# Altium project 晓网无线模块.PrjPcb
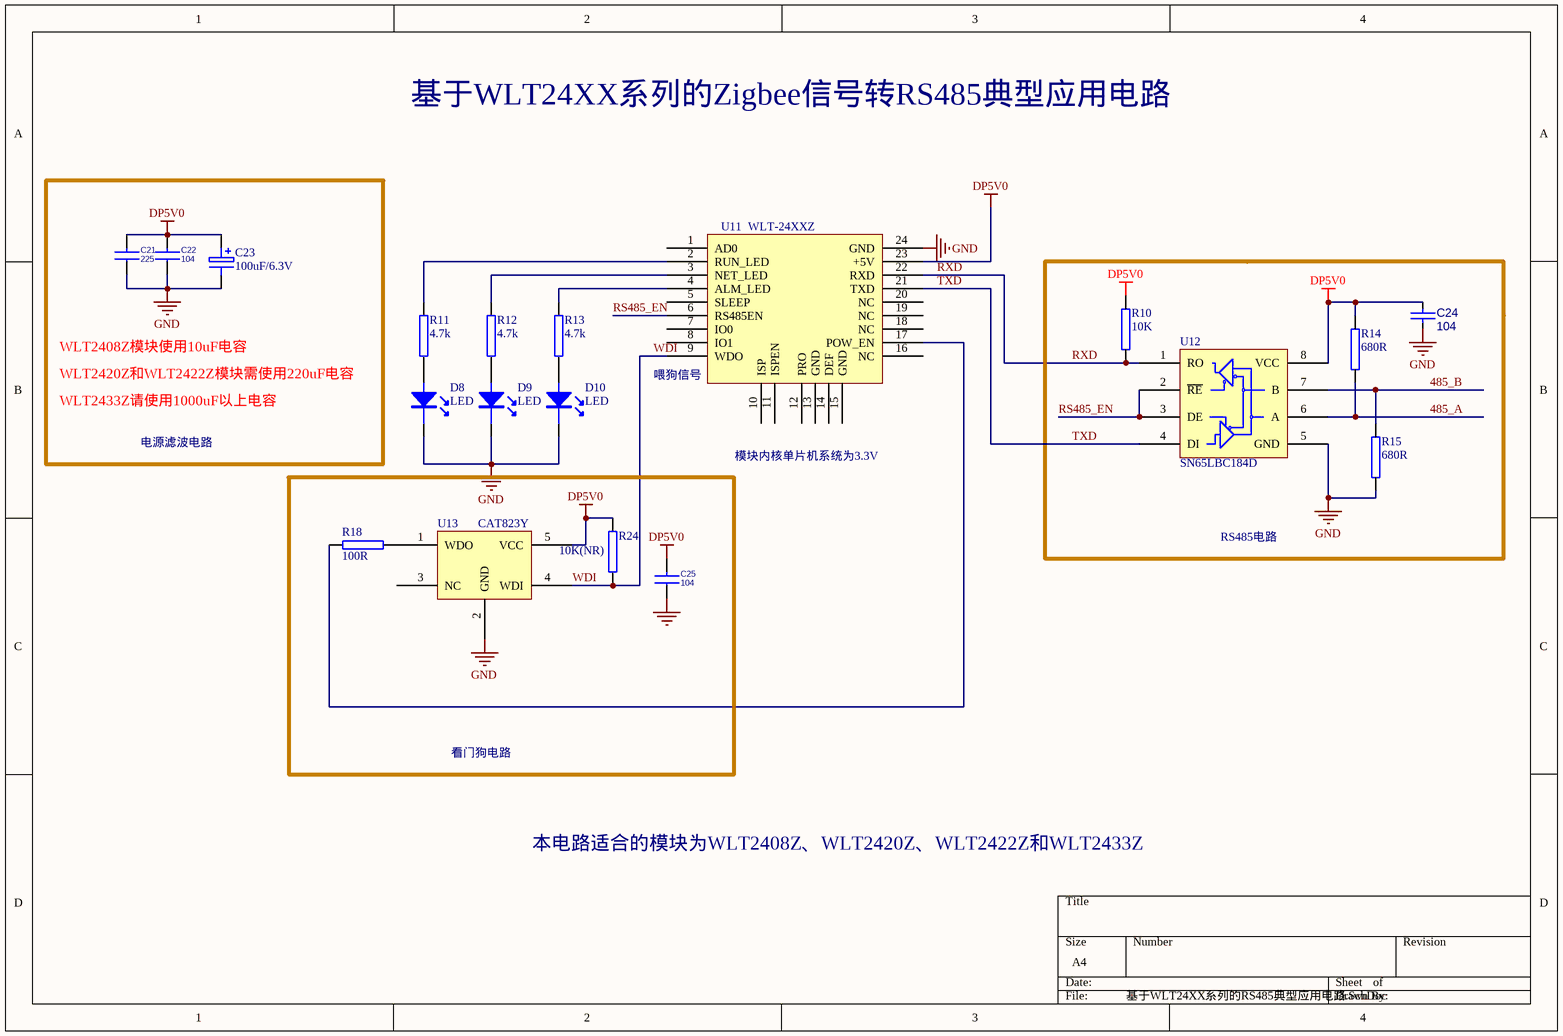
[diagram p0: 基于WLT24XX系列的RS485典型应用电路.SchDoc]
6 sheets, 113 parts. Net scope: flat (ports and power ports of the same name join across sheets).
Sheets:
  基于WLT24XX系列的RS485典型应用电路.SchDoc
  WLT24XXSZ（邮票孔封装）典型应用电路.SchDoc
  基于WLT24XX系列的RS232典型应用电路.SchDoc
  WLT24XXZ系列（双排直插）最小系统电路.SchDoc
  WLT2420NZ（直插）典型应用电路.SchDoc
  WLT2408NZ（直插）典型应用电路.SchDoc

## Sheet 基于WLT24XX系列的RS485典型应用电路.SchDoc
size A4

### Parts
(Parts that share a designator on the sheet are numbered #1, #2 ... from top to bottom, then left to right.)
C21  225  [0603C]
C22  104  [0603C]
C23  100uF/6.3V  [RB-.3/.6]
C24  104  [0603C]
C25  104  [0603C]
D8#1  LED  [LED-0805]
D9#1  LED  [LED-0805]
D10#1  LED  [LED-0805]
R10  10K  [0603R]
R11#1  4.7k  [0603R]
R12#1  4.7k  [0603R]
R13#1  4.7k  [0603R]
R14  680R  [0603R]
R15  680R  [0603R]
R18  100R  [0603R]
R24  10K(NR)  [0603R]
U11#1  WLT-24XXZ  [WLT-24XX]
U12  SN65LBC184D  [SO-8]
U13  CAT823Y  [SOT-23-5]

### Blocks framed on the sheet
RS485电路: C24 R10 R14 R15 U12

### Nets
DP5V0: C21.2 C22.2 C23.1 C24.1 C25.2 R10.2 R14.2 R24.1 U11#1.23(+5V) U12.8(VCC) U13.5(VCC)
GND: C21.1 C22.1 C23.2 C24.2 C25.1 D8#1.2 D9#1.2 D10#1.2 R15.1 U11#1.24(GND) U12.5(GND) U13.2(GND)
485_A: R14.1 U12.6(A)
485_B: R15.2 U12.7(B)
RS485_EN: U11#1.6(RS485EN) U12.2(~{RE}) U12.3(DE)
RXD: R10.1 U11#1.22(RXD) U12.1(RO)
TXD: U11#1.21(TXD) U12.4(DI)
WDI: R24.2 U11#1.9(WDO) U13.4(WDI)
NetD8#1_1: D8#1.1 R11#1.1
NetD9#1_1: D9#1.1 R12#1.1
NetD10#1_1: D10#1.1 R13#1.1
NetR11#1_2: R11#1.2 U11#1.2(RUN_LED)
NetR12#1_2: R12#1.2 U11#1.3(NET_LED)
NetR13#1_2: R13#1.2 U11#1.4(ALM_LED)
NetR18_1: R18.1 U13.1(WDO)
NetR18_2: R18.2 U11#1.17(POW_EN)

Not connected (* = marked no-connect by the designer): U11#1 1(AD0) 5(SLEEP) 7(IO0) 8(IO1) 10(ISP) 11(ISPEN) 12(PRO) 13(GND) 14(DEF) 15(GND) 16(NC) 18(NC) 19(NC) 20(NC); U13 3(NC)

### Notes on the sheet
- 基于WLT24XX系列的Zigbee信号转RS485典型应用电路
- WLT2420Z和WLT2422Z模块需使用220uF电容
- WLT2408Z模块使用10uF电容
- (near U11#1) 喂狗信号
- WLT2433Z请使用1000uF以上电容
- 电源滤波电路
- 模块内核单片机系统为3.3V
- 看门狗电路
- 本电路适合的模块为WLT2408Z、WLT2420Z、WLT2422Z和WLT2433Z

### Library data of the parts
C21 C22 C25 = CAP NP
C23 = CAP ELECTRO1: Electrolytic Capacitor
C24 = CAP
R10 R14 R15 = RES1
R11#1 R12#1 R13#1 R18 R24 = RES2
U11#1 = WLT-24
U12 = MAX485CSA
U13 = CAT6219

## Sheet WLT24XXSZ（邮票孔封装）典型应用电路.SchDoc
size A4; Revision: V1.01
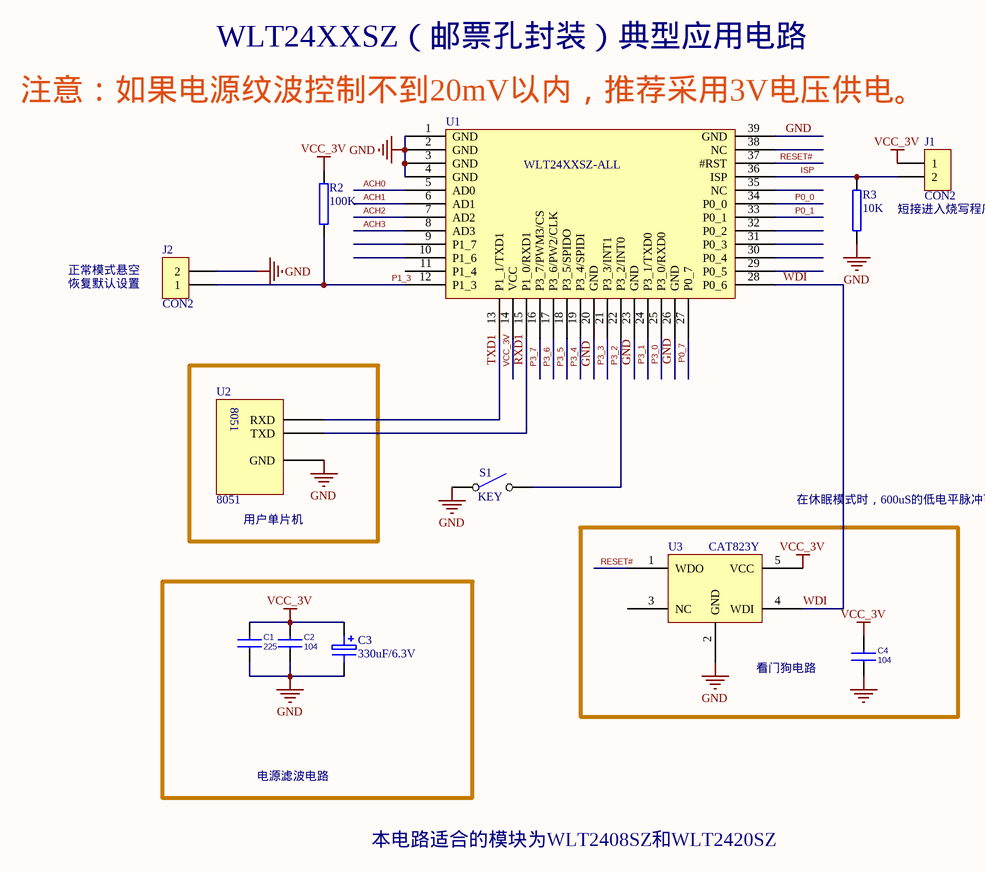
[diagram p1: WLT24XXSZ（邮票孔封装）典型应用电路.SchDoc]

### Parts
(Parts that share a designator on the sheet are numbered #1, #2 ... from top to bottom, then left to right.)
C1#1  225  [0603C]
C2#1  104  [0603C]
C3#1  330uF/6.3V  [RB-.3/.6]
C4#1  104  [0603C]
J1#1  CON2  [SIP-2]
J2#1  CON2  [SIP-2]
R2#1  100K  [0805R]
R3#1  10K  [0805R]
S1  KEY
U1  WLT24XXSZ-ALL  [WLT24xxSZ-SMD]
U2#1  8051
U3#1  CAT823Y  [SOT-23-5]

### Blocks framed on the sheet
用户单片机: U2#1
看门狗电路: C4#1 U3#1
电源滤波电路: C1#1 C2#1 C3#1

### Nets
GND: C1#1.1 C2#1.1 C3#1.2 C4#1.1 J2#1.2 R3#1.2 S1.1(COMMON) U1.1(GND) U1.2(GND) U1.3(GND) U1.4(GND) U1.20(GND) U1.23(GND) U1.26(GND) U1.39(GND) U2#1.?3(GND) U3#1.2(GND)
VCC_3V: C1#1.2 C2#1.2 C3#1.1 C4#1.2 J1#1.1 R2#1.2 U1.14(VCC) U3#1.5(VCC)
ACH0: U1.5(AD0)
ACH1: U1.6(AD1)
ACH2: U1.7(AD2)
ACH3: U1.8(AD3)
ISP: J1#1.2 R3#1.1 U1.36(ISP)
P0_0: U1.34(P0_0)
P0_1: U1.33(P0_1)
P0_7: U1.27(P0_7)
P1_3: J2#1.1 R2#1.1 U1.12(P1_3)
P3_0: U1.25(P3_0/RXD0)
P3_1: U1.24(P3_1/TXD0)
P3_2: S1.2(NO) U1.22(P3_2/INT0)
P3_3: U1.21(P3_3/INT1)
P3_4: U1.19(P3_4/SPIDI)
P3_5: U1.18(P3_5/SPIDO)
P3_6: U1.17(P3_6/PW2/CLK)
P3_7: U1.16(P3_7/PWM3/CS)
RESET#: U1.37(#RST) U3#1.1(WDO)
RXD1: U1.15(P1_0/RXD1) U2#1.?1(TXD)
TXD1: U1.13(P1_1/TXD1) U2#1.?2(RXD)
WDI: U1.28(P0_6) U3#1.4(WDI)

Not connected (* = marked no-connect by the designer): U1 9(P1_7) 10(P1_6) 11(P1_4) 29(P0_5) 30(P0_4) 31(P0_3) 32(P0_2) 35(NC) 38(NC); U3#1 3(NC)

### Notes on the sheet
- WLT24XXSZ（邮票孔封装）典型应用电路
- (near U1) 注意：如果电源纹波控制不到20mV以内，推荐采用3V电压供电。
- 短接进入烧写程序模式
- 恢复默认设置
- 正常模式悬空
- 在休眠模式时，600uS的低电平脉冲可唤醒MCU
- 本电路适合的模块为WLT2408SZ和WLT2420SZ

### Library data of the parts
C1#1 C2#1 C4#1 = CAP NP
C3#1 = CAP ELECTRO1: Electrolytic Capacitor
J1#1 J2#1 = CON2: Connector
R2#1 R3#1 = RES2
S1 = SW SPST
U3#1 = CAT6219

## Sheet 基于WLT24XX系列的RS232典型应用电路.SchDoc
size A4
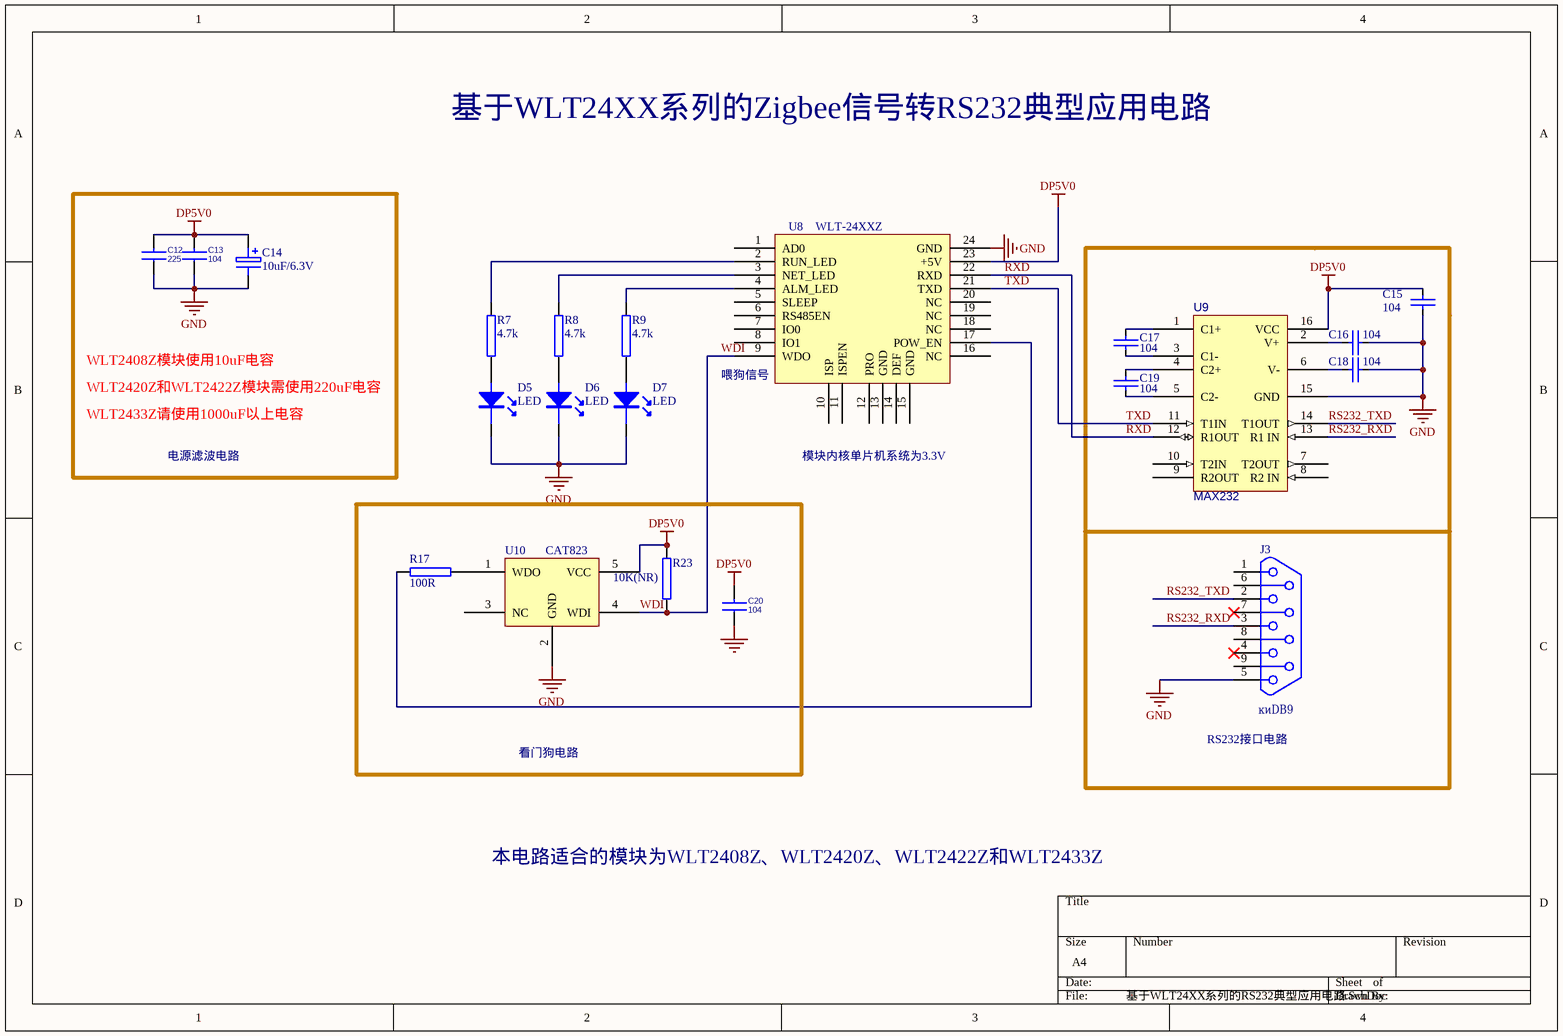
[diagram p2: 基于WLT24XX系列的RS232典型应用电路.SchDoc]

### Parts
C12  225  [0603C]
C13  104  [0603C]
C14  10uF/6.3V  [RB-.3/.6]
C15  104  [0603C]
C16  104  [0603C]
C17  104  [0603C]
C18  104  [0603C]
C19  104  [0603C]
C20  104  [0603C]
D5  LED  [LED-0805]
D6  LED  [LED-0805]
D7  LED  [LED-0805]
J3  ĸͷDB9  [DB-9RA/F]
R7  4.7k  [0603R]
R8  4.7k  [0603R]
R9  4.7k  [0603R]
R17  100R  [0603R]
R23  10K(NR)  [0603R]
U8  WLT-24XXZ  [WLT-24XX]
U9  MAX232  [TSSOP-16]
U10  CAT823  [SOT-23-5]

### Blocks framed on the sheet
RS232接口电路: C15-C19 J3 U9
看门狗电路: C20 R17 R23 U10

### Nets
DP5V0: C12.2 C13.2 C14.1 C15.2 C20.2 R23.1 U8.23(+5V) U9.16(VCC) U10.5(VCC)
GND: C12.1 C13.1 C14.2 C15.1 C16.2 C18.1 C20.1 D5.2 D6.2 D7.2 J3.5 U8.24(GND) U9.15(GND) U10.2(GND)
RS232_RXD: J3.3 U9.13(R1_IN)
RS232_TXD: J3.2 U9.14(T1OUT)
RXD: U8.22(RXD) U9.12(R1OUT)
TXD: U8.21(TXD) U9.11(T1IN)
WDI: R23.2 U8.9(WDO) U10.4(WDI)
NetC16_1: C16.1 U9.2(V+)
NetC17_1: C17.1 U9.3(C1-)
NetC17_2: C17.2 U9.1(C1+)
NetC18_2: C18.2 U9.6(V-)
NetC19_1: C19.1 U9.5(C2-)
NetC19_2: C19.2 U9.4(C2+)
NetD5_1: D5.1 R7.1
NetD6_1: D6.1 R8.1
NetD7_1: D7.1 R9.1
NetR7_2: R7.2 U8.2(RUN_LED)
NetR8_2: R8.2 U8.3(NET_LED)
NetR9_2: R9.2 U8.4(ALM_LED)
NetR17_1: R17.1 U10.1(WDO)
NetR17_2: R17.2 U8.17(POW_EN)

Not connected (* = marked no-connect by the designer): J3 1 4* 6 7* 8 9; U8 1(AD0) 5(SLEEP) 6(RS485EN) 7(IO0) 8(IO1) 10(ISP) 11(ISPEN) 12(PRO) 13(GND) 14(DEF) 15(GND) 16(NC) 18(NC) 19(NC) 20(NC); U9 7(T2OUT) 8(R2_IN) 9(R2OUT) 10(T2IN); U10 3(NC)

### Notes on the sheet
- 基于WLT24XX系列的Zigbee信号转RS232典型应用电路
- WLT2408Z模块使用10uF电容
- (near U8) 喂狗信号
- WLT2420Z和WLT2422Z模块需使用220uF电容
- WLT2433Z请使用1000uF以上电容
- 电源滤波电路
- 模块内核单片机系统为3.3V
- 本电路适合的模块为WLT2408Z、WLT2420Z、WLT2422Z和WLT2433Z

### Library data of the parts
C12 C13 C20 = CAP NP
C14 = CAP ELECTRO1: Electrolytic Capacitor
C15-C19 = CAP
J3 = DB9
R7-R9 R17 R23 = RES2
U8 = WLT-24
U9 = MAX232CPE(16)_1: +-15KV ESD-PROTECTED, +5V RS-232 TRANSCEIVERS
U10 = CAT6219

## Sheet WLT24XXZ系列（双排直插）最小系统电路.SchDoc
size A4
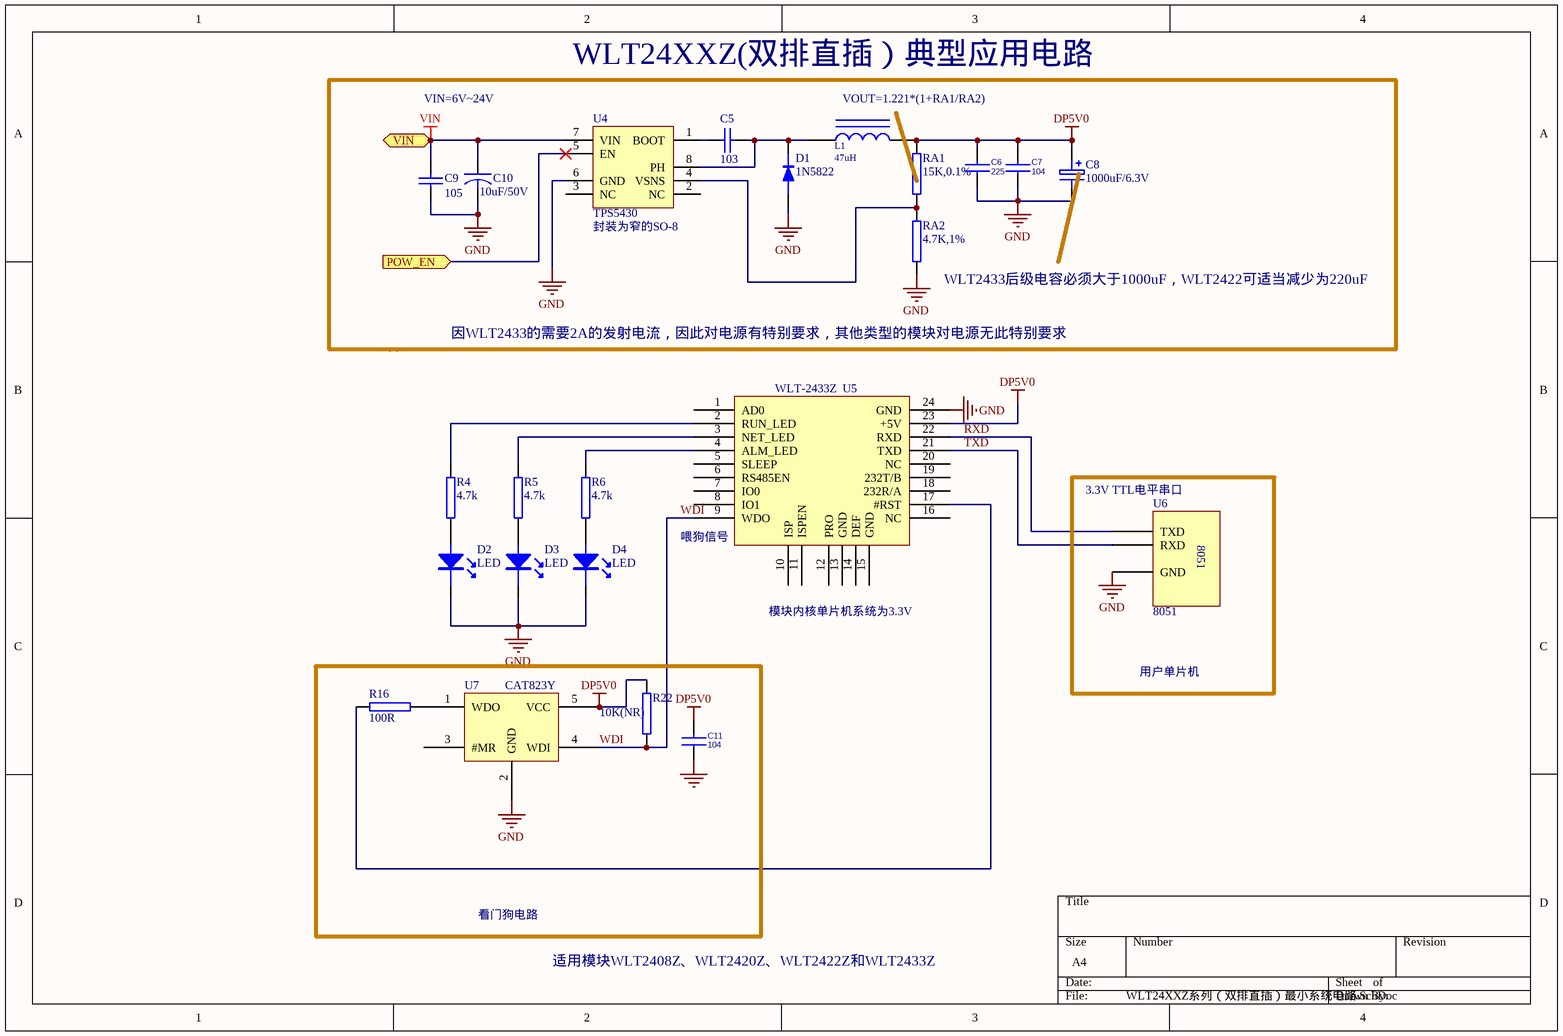
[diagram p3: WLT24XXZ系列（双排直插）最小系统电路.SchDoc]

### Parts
C5  103  [0603C]
C6  225  [0603C]
C7  104  [0603C]
C8  1000uF/6.3V  [RB-.2/.4]
C9  105  [0603C]
C10  10uF/50V  [CAP-A]
C11  104  [0603C]
D1  1N5822  [DIODE-0.7]
D2  LED  [LED-0805]
D3  LED  [LED-0805]
D4  LED  [LED-0805]
L1  47uH  [L-12X12S]
R4  4.7k  [0603R]
R5  4.7k  [0603R]
R6  4.7k  [0603R]
R16  100R  [0603R]
R22  10K(NR)  [0603R]
RA1  15K,0.1%  [0603R]
RA2  4.7K,1%  [0603R]
U4  TPS5430  [TPS5430]
U5  WLT-2433Z  [WLT-24XX]
U6  8051
U7  CAT823Y  [SOT-23-5]

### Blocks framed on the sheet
看门狗电路: C11 R16 R22 U7

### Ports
POW_EN (in), VIN (in)

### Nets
DP5V0: C6.2 C7.2 C8.1 C11.2 L1.2 R22.1 RA1.2 U5.23(+5V) U7.5(VCC)
GND: C6.1 C7.1 C8.2 C9.2 C10.2 C11.1 D1.1(K) D2.2 D3.2 D4.2 RA2.1 U4.6(GND) U5.24(GND) U6.?3(GND) U7.2(GND)
VIN: C9.1 C10.1 U4.7(VIN) ; port VIN
RXD: U5.22(RXD) U6.?1(TXD)
TXD: U5.21(TXD) U6.?2(RXD)
WDI: R22.2 U5.9(WDO) U7.4(WDI)
NetC5_1: C5.1 U4.1(BOOT)
NetC5_2: C5.2 D1.2(A) L1.1 U4.8(PH)
NetD2_1: D2.1 R4.1
NetD3_1: D3.1 R5.1
NetD4_1: D4.1 R6.1
NetR4_2: R4.2 U5.2(RUN_LED)
NetR5_2: R5.2 U5.3(NET_LED)
NetR6_2: R6.2 U5.4(ALM_LED)
NetR16_1: R16.1 U7.1(WDO)
NetR16_2: R16.2 U5.17(#RST)
NetRA1_1: RA1.1 RA2.2 U4.4(VSNS)
NetU4_5: U4.5(EN) ; port POW_EN

Not connected (* = marked no-connect by the designer): U4 2(NC) 3(NC); U5 1(AD0) 5(SLEEP) 6(RS485EN) 7(IO0) 8(IO1) 10(ISP) 11(ISPEN) 12(PRO) 13(GND) 14(DEF) 15(GND) 16(NC) 18(232R/A) 19(232T/B) 20(NC); U7 3(#MR)

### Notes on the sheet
- VIN=6V|4V
- WLT24XXZ(双排直插）典型应用电路
- VOUT=1.221*(1+RA1/RA2)
- (near U4) 封装为窄的SO-8
- (near RA2) WLT2433后级电容必须大于1000uF，WLT2422可适当减少为220uF
- 因WLT2433的需要2A的发射电流，因此对电源有特别要求，其他类型的模块对电源无此特别要求
- (near U6) 3.3V TTL电平串口
- (near U5) 喂狗信号
- 模块内核单片机系统为3.3V
- 用户单片机
- 适用模块WLT2408Z、WLT2420Z、WLT2422Z和WLT2433Z

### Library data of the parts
C5 C9 = CAP: Capacitor
C6 C7 C11 = CAP NP
C8 = CAP ELECTRO1: Electrolytic Capacitor
C10 = CAPACITOR
D1 = 1N5819S
L1 = INDUCTOR IRON
R4-R6 R16 R22 RA1 RA2 = RES2
U4 = TPS5410
U5 = WLT-24
U7 = CAT6219

## Sheet WLT2420NZ（直插）典型应用电路.SchDoc
size A4; Revision: V1.01
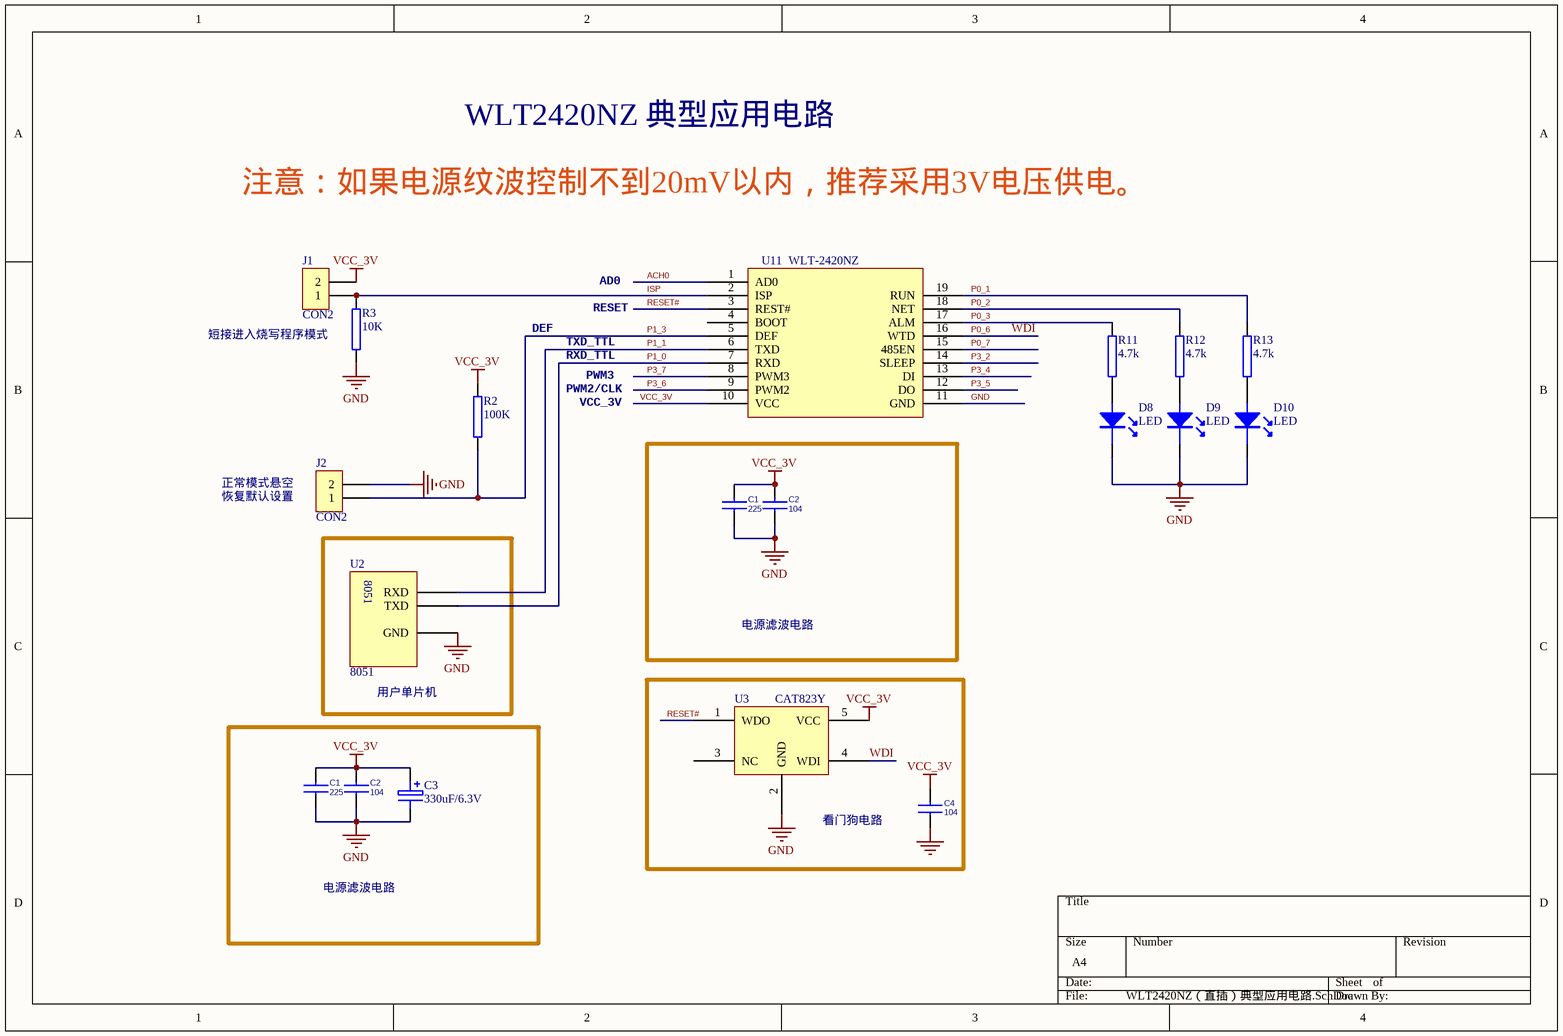
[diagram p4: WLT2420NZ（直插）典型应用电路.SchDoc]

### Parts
(Parts that share a designator on the sheet are numbered #1, #2 ... from top to bottom, then left to right.)
C1#2  225  [0603C]
C1#3  225  [0603C]
C2#2  104  [0603C]
C2#3  104  [0603C]
C3#2  330uF/6.3V  [RB-.3/.6]
C4#2  104  [0603C]
D8#2  LED  [LED-0805]
D9#2  LED  [LED-0805]
D10#2  LED  [LED-0805]
J1#2  CON2  [SIP-2]
J2#2  CON2  [SIP-2]
R2#2  100K  [0805R]
R3#2  10K  [0805R]
R11#2  4.7k  [0603R]
R12#2  4.7k  [0603R]
R13#2  4.7k  [0603R]
U2#2  8051
U3#2  CAT823Y  [SOT-23-5]
U11#2  WLT-2420NZ  [WLT2420NZ]

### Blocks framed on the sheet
电源滤波电路: C1#2 C2#2
用户单片机: U2#2
电源滤波电路: C1#3 C2#3 C3#2
看门狗电路: C4#2 U3#2

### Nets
GND: C1#2.1 C1#3.1 C2#2.1 C2#3.1 C3#2.2 C4#2.1 D8#2.2 D9#2.2 D10#2.2 J2#2.2 R3#2.2 U2#2.?3(GND) U3#2.2(GND) U11#2.11(GND)
VCC_3V: C1#2.2 C1#3.2 C2#2.2 C2#3.2 C3#2.1 C4#2.2 J1#2.2 R2#2.2 U3#2.5(VCC) U11#2.10(VCC)
ACH0: U11#2.1(AD0)
ISP: J1#2.1 R3#2.1 U11#2.2(ISP)
P0_1: R13#2.2 U11#2.19(RUN)
P0_2: R12#2.2 U11#2.18(NET)
P0_3: R11#2.2 U11#2.17(ALM)
P0_6: U3#2.4(WDI) U11#2.16(WTD)  [also labelled WDI]
P0_7: U11#2.15(485EN)
P1_0: U2#2.?1(TXD) U11#2.7(RXD)
P1_1: U2#2.?2(RXD) U11#2.6(TXD)
P1_3: J2#2.1 R2#2.1 U11#2.5(DEF)
P3_2: U11#2.14(SLEEP)
P3_4: U11#2.13(DI)
P3_5: U11#2.12(DO)
P3_6: U11#2.9(PWM2)
P3_7: U11#2.8(PWM3)
RESET#: U3#2.1(WDO) U11#2.3(REST#)
NetD8#2_1: D8#2.1 R11#2.1
NetD9#2_1: D9#2.1 R12#2.1
NetD10#2_1: D10#2.1 R13#2.1

Not connected (* = marked no-connect by the designer): U3#2 3(NC); U11#2 4(BOOT)

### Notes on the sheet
- WLT2420NZ 典型应用电路
- 注意：如果电源纹波控制不到20mV以内，推荐采用3V电压供电。
- RESET
- AD0
- 短接进入烧写程序模式
- DEF
- RXD_TTL
- TXD_TTL
- PWM3
- PWM2/CLK
- VCC_3V
- 恢复默认设置
- 正常模式悬空

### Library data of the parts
C1#2 C1#3 C2#2 C2#3 C4#2 = CAP NP
C3#2 = CAP ELECTRO1: Electrolytic Capacitor
J1#2 J2#2 = CON2: Connector
R2#2 R3#2 R11#2 R12#2 R13#2 = RES2
U3#2 = CAT6219
U11#2 = WLT-24

## Sheet WLT2408NZ（直插）典型应用电路.SchDoc
size A4; Revision: V1.01
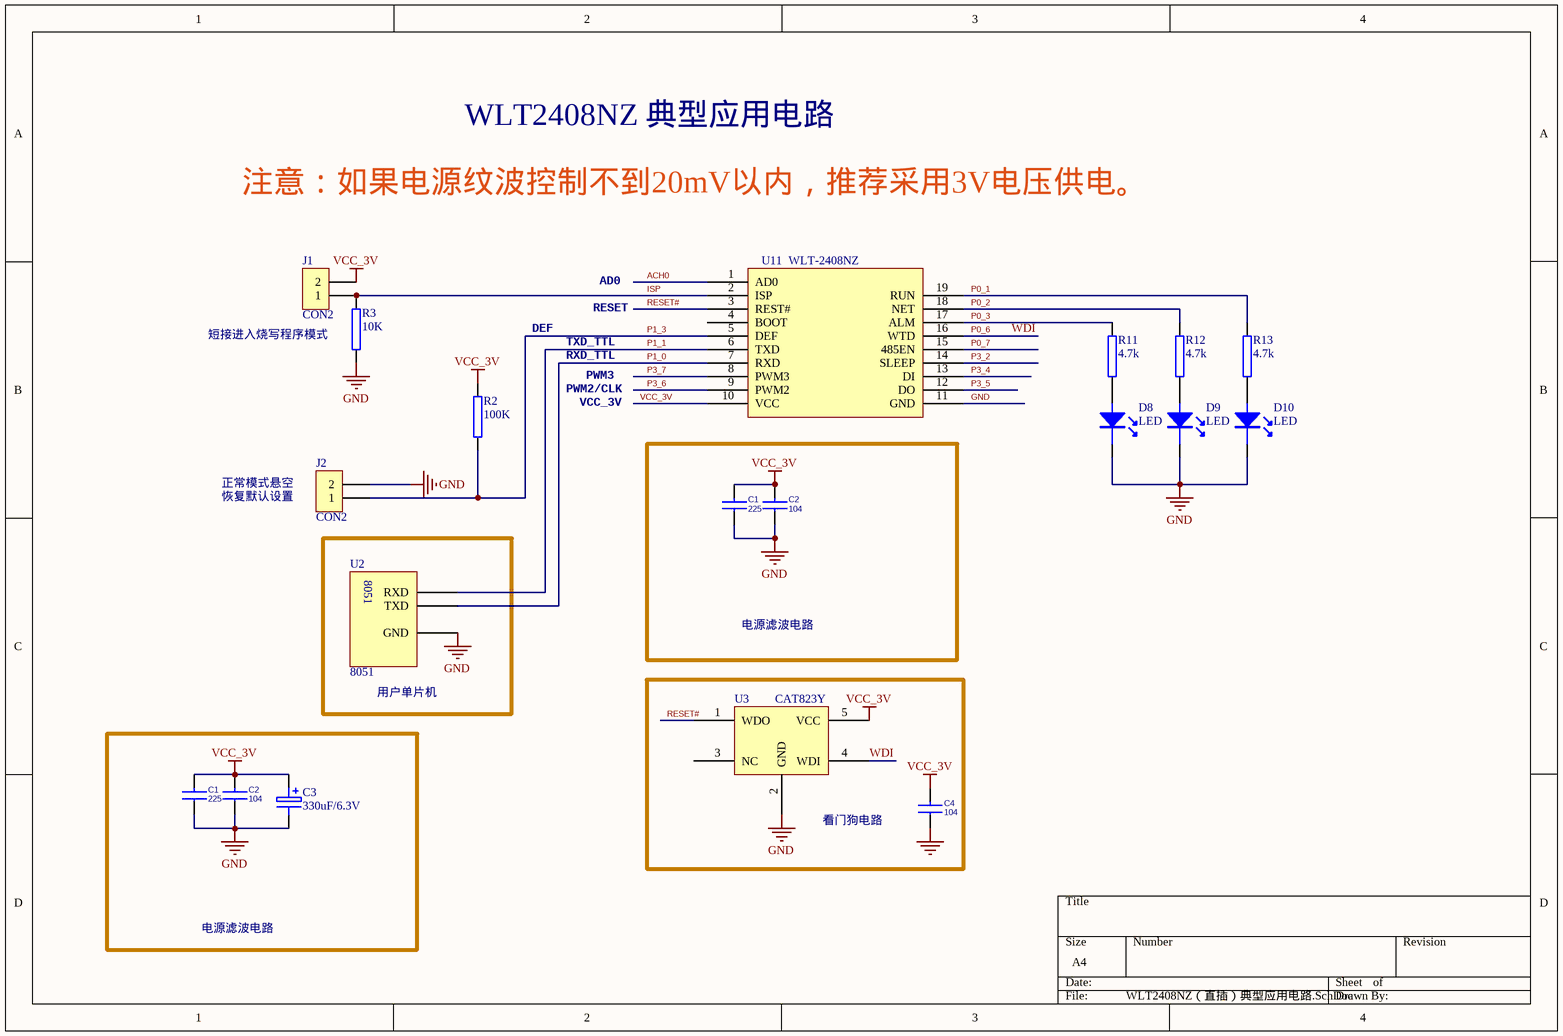
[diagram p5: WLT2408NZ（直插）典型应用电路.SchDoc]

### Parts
(Parts that share a designator on the sheet are numbered #1, #2 ... from top to bottom, then left to right.)
C1#4  225  [0603C]
C1#5  225  [0603C]
C2#4  104  [0603C]
C2#5  104  [0603C]
C3#3  330uF/6.3V  [RB-.3/.6]
C4#3  104  [0603C]
D8#3  LED  [LED-0805]
D9#3  LED  [LED-0805]
D10#3  LED  [LED-0805]
J1#3  CON2  [SIP-2]
J2#3  CON2  [SIP-2]
R2#3  100K  [0805R]
R3#3  10K  [0805R]
R11#3  4.7k  [0603R]
R12#3  4.7k  [0603R]
R13#3  4.7k  [0603R]
U2#3  8051
U3#3  CAT823Y  [SOT-23-5]
U11#3  WLT-2408NZ  [WLT-24XX]

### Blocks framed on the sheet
电源滤波电路: C1#4 C2#4
用户单片机: U2#3
电源滤波电路: C1#5 C2#5 C3#3
看门狗电路: C4#3 U3#3

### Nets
GND: C1#4.1 C1#5.1 C2#4.1 C2#5.1 C3#3.2 C4#3.1 D8#3.2 D9#3.2 D10#3.2 J2#3.2 R3#3.2 U2#3.?3(GND) U3#3.2(GND) U11#3.11(GND)
VCC_3V: C1#4.2 C1#5.2 C2#4.2 C2#5.2 C3#3.1 C4#3.2 J1#3.2 R2#3.2 U3#3.5(VCC) U11#3.10(VCC)
ACH0: U11#3.1(AD0)
ISP: J1#3.1 R3#3.1 U11#3.2(ISP)
P0_1: R13#3.2 U11#3.19(RUN)
P0_2: R12#3.2 U11#3.18(NET)
P0_3: R11#3.2 U11#3.17(ALM)
P0_6: U3#3.4(WDI) U11#3.16(WTD)  [also labelled WDI]
P0_7: U11#3.15(485EN)
P1_0: U2#3.?1(TXD) U11#3.7(RXD)
P1_1: U2#3.?2(RXD) U11#3.6(TXD)
P1_3: J2#3.1 R2#3.1 U11#3.5(DEF)
P3_2: U11#3.14(SLEEP)
P3_4: U11#3.13(DI)
P3_5: U11#3.12(DO)
P3_6: U11#3.9(PWM2)
P3_7: U11#3.8(PWM3)
RESET#: U3#3.1(WDO) U11#3.3(REST#)
NetD8#3_1: D8#3.1 R11#3.1
NetD9#3_1: D9#3.1 R12#3.1
NetD10#3_1: D10#3.1 R13#3.1

Not connected (* = marked no-connect by the designer): U3#3 3(NC); U11#3 4(BOOT)

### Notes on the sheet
- WLT2408NZ 典型应用电路
- 注意：如果电源纹波控制不到20mV以内，推荐采用3V电压供电。
- RESET
- AD0
- 短接进入烧写程序模式
- DEF
- RXD_TTL
- TXD_TTL
- PWM3
- PWM2/CLK
- VCC_3V
- 恢复默认设置
- 正常模式悬空

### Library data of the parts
C1#4 C1#5 C2#4 C2#5 C4#3 = CAP NP
C3#3 = CAP ELECTRO1: Electrolytic Capacitor
J1#3 J2#3 = CON2: Connector
R2#3 R3#3 R11#3 R12#3 R13#3 = RES2
U3#3 = CAT6219
U11#3 = WLT-24

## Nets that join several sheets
DP5V0: 基于WLT24XX系列的RS485典型应用电路 (11 pins), 基于WLT24XX系列的RS232典型应用电路 (9 pins), WLT24XXZ系列（双排直插）最小系统电路 (9 pins)
GND: 基于WLT24XX系列的RS485典型应用电路 (12 pins), WLT24XXSZ（邮票孔封装）典型应用电路 (17 pins), 基于WLT24XX系列的RS232典型应用电路 (14 pins), WLT24XXZ系列（双排直插）最小系统电路 (15 pins), WLT2420NZ（直插）典型应用电路 (14 pins), WLT2408NZ（直插）典型应用电路 (14 pins)
VCC_3V: WLT24XXSZ（邮票孔封装）典型应用电路 (8 pins), WLT2420NZ（直插）典型应用电路 (10 pins), WLT2408NZ（直插）典型应用电路 (10 pins)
